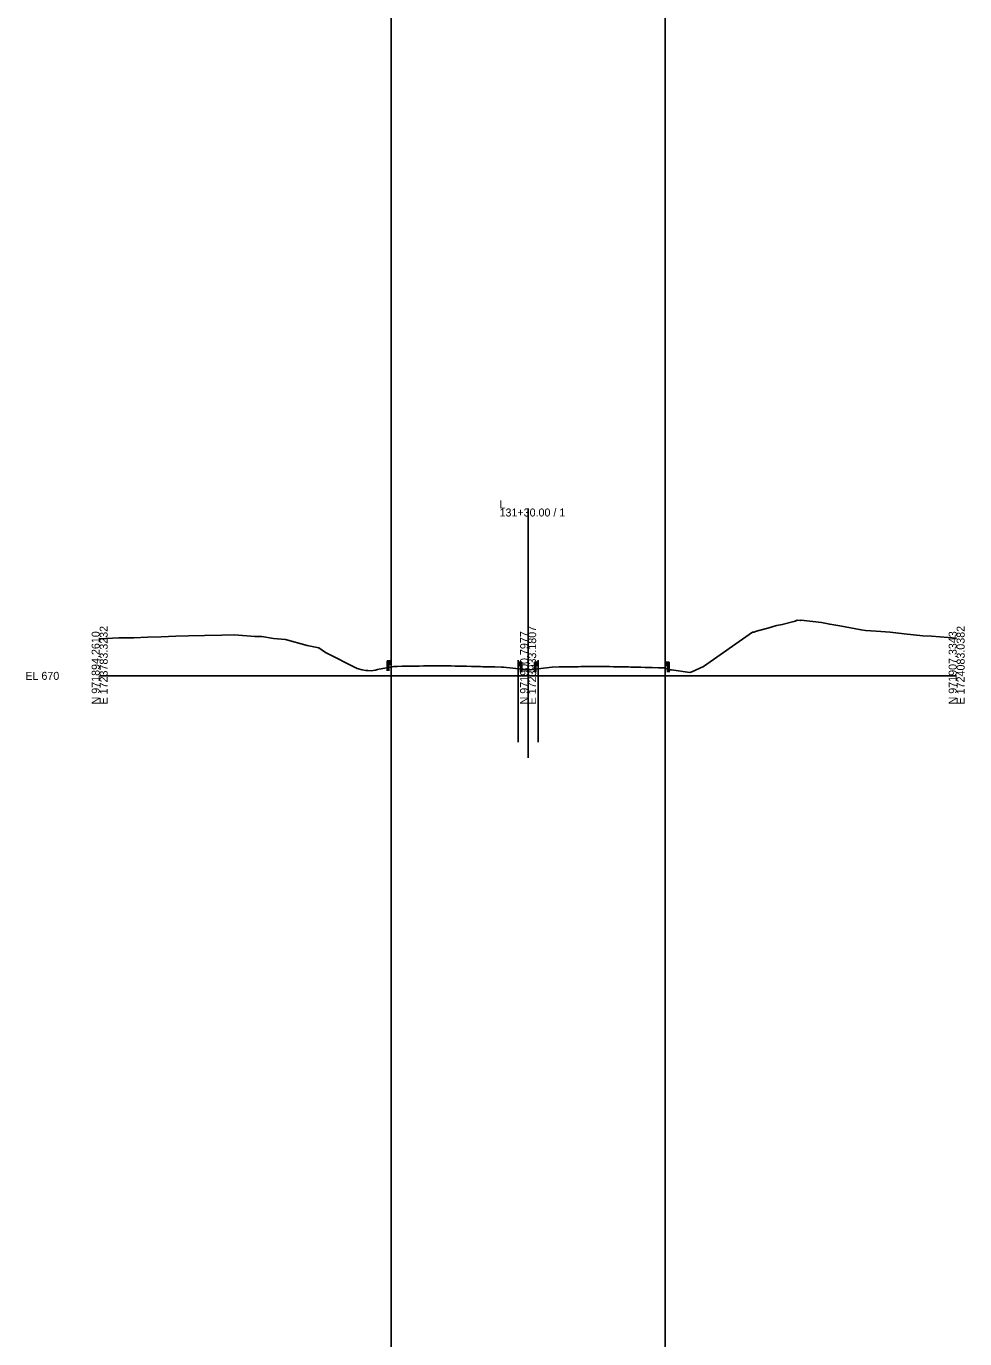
# Model space of a CAD drawing. Extents: x -26 to 303, y -29 to 15026.
# Drawn here: x -25.7 to 302.8, y 2268 to 2727.3 of the extents above; entities that cross this region are included whole.
import ezdxf

# ---------------------------------------------------------------- set-up
doc = ezdxf.new("R2010")
doc.units = 0
for name, color, linetype in [('Exist Cross Section Cell', 7, 'Continuous'), ('Exist XS Center Line Elevation Label', 7, 'Continuous'), ('Exist XS Ground Line', 7, 'Continuous'), ('Scratch_Level_0', 7, 'Continuous'), ('Typical Guardrail CELL', 7, 'Continuous')]:
    doc.layers.add(name, color=color, linetype=linetype)

msp = doc.modelspace()

# ---------------------------------------------------------------- linework, layer by layer
at = {"layer": 'Exist Cross Section Cell'}
for p, q in [((150, 2500), (150, 2558.57)), ((0, 2500), (150, 2500)), ((150, 2500), (300, 2500))]:
    msp.add_line(p, q, dxfattribs=at)
at = {"layer": 'Exist XS Ground Line'}
msp.add_lwpolyline([(0, 2513), (2.33, 2513.13), (6.7, 2513.26), (11.92, 2513.36), (16.7, 2513.49), (21.51, 2513.6), (26.71, 2513.84), (31.1, 2514.04), (36.72, 2514.08), (42.81, 2514.29), (47.26, 2514.37), (54.38, 2513.75), (56.74, 2513.72), (60.88, 2513.08), (65.11, 2512.72), (72.62, 2510.62), (76.76, 2509.8), (79.06, 2508.19), (90.2, 2502.62), (91.86, 2502.06), (93.2, 2501.83), (93.94, 2501.83), (95.03, 2501.76), (95.76, 2501.89), (96.6, 2501.98), (97.22, 2502.18), (103, 2503.23), (103.59, 2503.29), (104.2, 2503.31), (105.87, 2503.36), (107.57, 2503.39), (108.38, 2503.41), (109.27, 2503.42), (111.16, 2503.44), (111.91, 2503.44), (113.4, 2503.45), (114.78, 2503.46), (115.89, 2503.46), (117.1, 2503.47), (118.39, 2503.48), (119.72, 2503.47), (120.88, 2503.46), (122.1, 2503.46), (123.06, 2503.46), (124.49, 2503.43), (125.87, 2503.4), (127.54, 2503.36), (128.37, 2503.34), (130.17, 2503.31), (130.87, 2503.3), (132.79, 2503.24), (133.38, 2503.23), (134.16, 2503.21), (135.76, 2503.17), (137.77, 2503.12), (138.39, 2503.11), (140.68, 2503.05), (141.33, 2503.03), (148.93, 2502.19), (149.56, 2502.13), (150.21, 2502.06), (150.86, 2502.13), (151.41, 2502.2), (158.43, 2503.07), (160.91, 2503.12), (162.72, 2503.15), (163.43, 2503.16), (163.77, 2503.17), (164.51, 2503.18), (165.34, 2503.19), (165.91, 2503.19), (167.51, 2503.21), (168.43, 2503.22), (169.44, 2503.23), (170.95, 2503.24), (172.31, 2503.25), (173.45, 2503.26), (174.68, 2503.26), (175.95, 2503.27), (176.87, 2503.27), (177.3, 2503.26), (177.62, 2503.26), (178.45, 2503.24), (179.9, 2503.21), (180.94, 2503.19), (181.88, 2503.18), (183.44, 2503.14), (185.13, 2503.1), (185.93, 2503.09), (186.66, 2503.07), (188.44, 2503.03), (189.48, 2503.01), (190.94, 2502.95), (191.47, 2502.94), (193.44, 2502.89), (195.63, 2502.83), (195.95, 2502.82), (196.66, 2502.8), (197.82, 2502.77), (198.13, 2502.57), (199.7, 2502.16), (200.14, 2502.12), (206.65, 2501.19), (207.27, 2501.42), (211.44, 2503.29), (228.53, 2515.25), (229, 2515.31), (229.9, 2515.59), (234.74, 2516.9), (235.75, 2517.23), (236.54, 2517.53), (237.03, 2517.64), (238.97, 2517.97), (243.01, 2518.97), (243.47, 2519.12), (244.2, 2519.51), (245.3, 2519.43), (245.63, 2519.52), (252.67, 2518.72), (255.56, 2518.07), (259.16, 2517.48), (266.56, 2516.08), (268.13, 2515.93), (271.85, 2515.66), (276.71, 2515.3), (281.61, 2514.67), (288.14, 2514.04), (291.25, 2513.87), (300, 2513.24)], dxfattribs=at)
at = {"layer": 'Scratch_Level_0'}
for p, q in [((102, 15009.56), (102, -28.7)), ((198, 15009.56), (198, -28.7)), ((146.46, 2505.5), (146.46, 2476.8)), ((153.54, 2505.5), (153.54, 2476.8)), ((150, 2500), (150, 2471.3))]:
    msp.add_line(p, q, dxfattribs=at)
at = {"layer": 'Typical Guardrail CELL'}
for p, q in [((101.18, 2505.3), (100.68, 2505.3)), ((100.68, 2505.3), (100.68, 2502.81)), ((101.18, 2505.3), (101.18, 2502.81)), ((101.18, 2505.3), (101.68, 2505.3)), ((101.18, 2504.14), (101.68, 2504.14)), ((101.68, 2505.3), (101.68, 2504.14)), ((101.68, 2505.3), (101.97, 2505.09)), ((101.68, 2504.76), (101.97, 2504.97)), ((101.68, 2504.72), (101.68, 2504.76)), ((101.68, 2504.72), (101.68, 2504.67)), ((101.68, 2504.67), (101.97, 2504.47)), ((101.68, 2504.14), (101.97, 2504.34)), ((146.78, 2504.81), (146.49, 2504.6)), ((146.78, 2504.27), (146.49, 2504.48)), ((146.78, 2504.18), (146.49, 2503.98)), ((146.78, 2503.65), (146.49, 2503.85)), ((147.28, 2504.81), (146.78, 2504.81)), ((146.78, 2504.81), (146.78, 2503.65)), ((146.78, 2504.23), (146.78, 2504.27)), ((146.78, 2504.23), (146.78, 2504.18)), ((147.28, 2503.65), (146.78, 2503.65)), ((147.28, 2504.81), (147.28, 2502.32)), ((147.28, 2504.81), (147.78, 2504.81)), ((147.78, 2504.81), (147.78, 2502.32)), ((152.72, 2504.78), (152.22, 2504.78)), ((152.22, 2504.78), (152.22, 2502.3)), ((152.72, 2504.78), (152.72, 2502.3)), ((152.72, 2504.78), (153.22, 2504.78)), ((152.72, 2503.62), (153.22, 2503.62)), ((153.22, 2504.78), (153.22, 2503.62)), ((153.22, 2504.78), (153.51, 2504.58)), ((153.22, 2504.25), (153.51, 2504.45)), ((153.22, 2504.2), (153.22, 2504.25)), ((153.22, 2504.2), (153.22, 2504.16)), ((153.22, 2504.16), (153.51, 2503.95)), ((153.22, 2503.62), (153.51, 2503.83)), ((198.32, 2504.75), (198.03, 2504.54)), ((198.32, 2504.21), (198.03, 2504.42)), ((198.32, 2504.12), (198.03, 2503.92)), ((198.32, 2503.59), (198.03, 2503.79)), ((198.82, 2504.75), (198.32, 2504.75)), ((198.32, 2504.75), (198.32, 2503.59)), ((198.32, 2504.17), (198.32, 2504.21)), ((198.32, 2504.17), (198.32, 2504.12)), ((198.82, 2503.59), (198.32, 2503.59)), ((198.82, 2504.75), (198.82, 2502.26)), ((198.82, 2504.75), (199.32, 2504.75)), ((199.32, 2504.75), (199.32, 2502.26)), ((101.18, 2502.81), (100.68, 2502.81)), ((100.68, 2502.81), (100.68, 2501.8)), ((101.18, 2502.81), (101.18, 2501.8)), ((147.28, 2502.32), (147.78, 2502.32)), ((147.28, 2502.32), (147.28, 2501.31)), ((147.78, 2502.32), (147.78, 2501.31)), ((152.72, 2502.3), (152.22, 2502.3)), ((152.22, 2502.3), (152.22, 2501.29)), ((152.72, 2502.3), (152.72, 2501.29)), ((198.82, 2502.26), (199.32, 2502.26)), ((198.82, 2502.26), (198.82, 2501.25)), ((199.32, 2502.26), (199.32, 2501.25))]:
    msp.add_line(p, q, dxfattribs=at)
for centre, start, end in [((101.92, 2505.03), 304.9888, 54.997), ((101.92, 2504.4), 304.9634, 54.9941), ((146.54, 2504.54), 125.003, 235.0112), ((146.54, 2503.91), 125.0059, 235.0366), ((153.46, 2504.52), 304.9888, 54.997), ((153.46, 2503.89), 304.9634, 54.9941), ((198.08, 2504.48), 125.003, 235.0112), ((198.08, 2503.85), 125.0059, 235.0366)]:
    msp.add_arc(centre, 0.0776, start, end, dxfattribs=at)

# ---------------------------------------------------------------- texts
at = {"layer": 'Exist Cross Section Cell'}
for s, p in [('131+30.00 / 1', (140, 2555.77)), ('L', (140, 2558.57)), ('EL 670', (-26, 2498.6))]:
    msp.add_text(s, height=2.8, dxfattribs=at).set_placement(p)
for s, p in [('E 1723783.3232', (2.8, 2490)), ('E 1723933.1807', (152.8, 2490)), ('E 1724083.0382', (302.8, 2490)), ('N 971894.2610', (0, 2490)), ('N 971900.7977', (150, 2490)), ('N 971907.3343', (300, 2490))]:
    msp.add_text(s, height=2.8, rotation=90, dxfattribs=at).set_placement(p)
at = {"layer": 'Exist XS Center Line Elevation Label'}
msp.add_text('672.08', height=0.18, dxfattribs=at).set_placement((149.62, 2501.59))

doc.saveas('drawing.dxf')
